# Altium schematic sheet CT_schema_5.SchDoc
size 284 x 211 mm
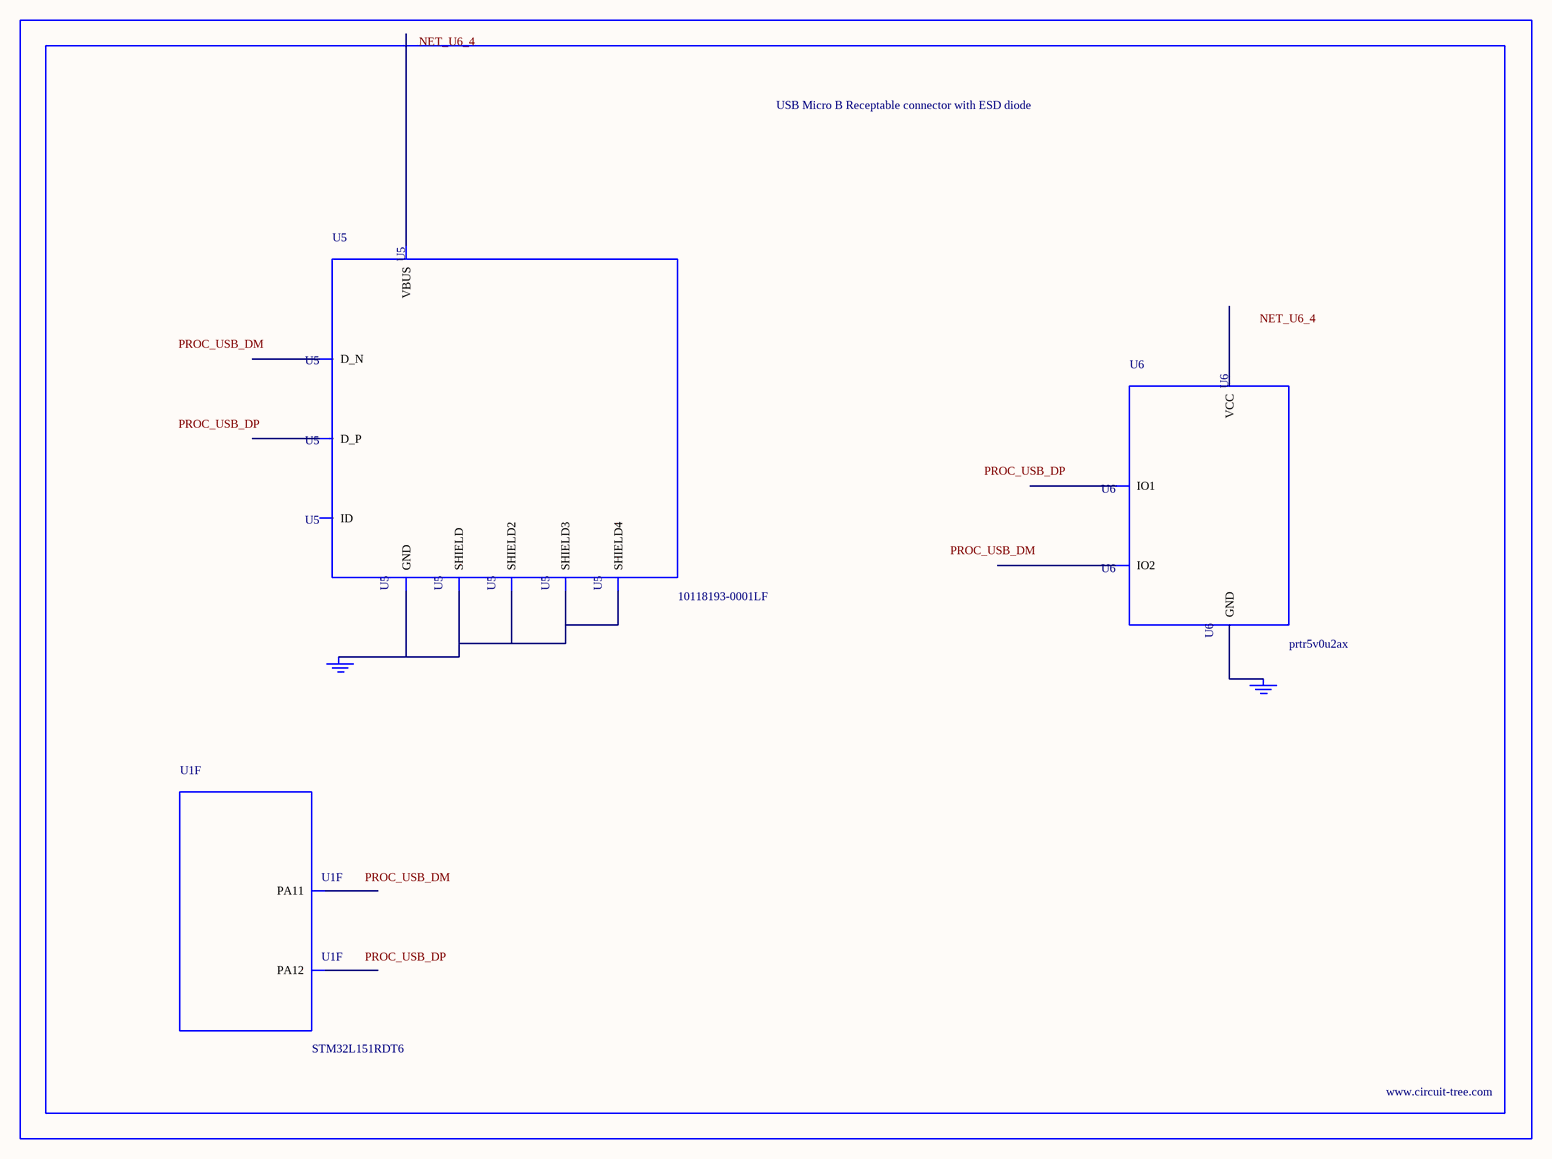
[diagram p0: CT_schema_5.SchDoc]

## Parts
BORDER4  (no value)
GND_INSTANCE_4_0  (no value)
GND_INSTANCE_4_1  (no value)
U1  STM32L151RDT6  [LQFP64]  (part F of 7)
U5  10118193-0001LF  [FCI_10118193-0001LF]
U6  prtr5v0u2ax  [SOT143B]

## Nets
NetGND_INSTANCE_4_0_0: GND_INSTANCE_4_0.0(GND) U5.5(GND) U5.6(SHIELD) U5.7(SHIELD2) U5.8(SHIELD3) U5.9(SHIELD4)
NetGND_INSTANCE_4_1_0: GND_INSTANCE_4_1.0(GND) U6.1(GND)

Not connected (* = marked no-connect by the designer): U1 44(PA11) 45(PA12); U5 1(VBUS) 2(D_N) 3(D_P) 4(ID); U6 2(IO1) 3(IO2) 4(VCC)

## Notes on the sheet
- Labels drawn without touching a wire or pin: NET_U6_4, PROC_USB_DM, PROC_USB_DP

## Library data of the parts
BORDER4 = BORDER_PAGE4
GND_INSTANCE_4_0 GND_INSTANCE_4_1 = GND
